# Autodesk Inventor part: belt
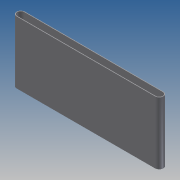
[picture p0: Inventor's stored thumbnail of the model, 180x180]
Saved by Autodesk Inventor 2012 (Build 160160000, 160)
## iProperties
Created: 2012-04
Part Number: belt
Material: Default
Document SubType Name: Modeling
Designer: win32
Mass: 4888.77 g
Surface Area: 19772.4 cm^2
Volume: 4888.77 cm^3
Density: 1 g/cm^3
Author: win32
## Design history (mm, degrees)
sketch "Sketch1"
  geometry: L1 (-244.095, 42.88)-(755.905, 42.88); L2 (755.905, 92.88)-(-244.095, 92.88); L3 (-244.095, 37.88)-(755.905, 37.88); L4 (755.905, 97.88)-(-244.095, 97.88); A1 r 25 centre (-244.095, 67.88) between (-244.095, 42.88) and (-244.095, 92.88) reference; A2 r 25 centre (755.905, 67.88) between (755.905, 42.88) and (755.905, 92.88) reference; A3 r 25 centre (755.905, 67.88) between (755.905, 42.88) and (755.905, 92.88); A4 r 25 centre (-244.095, 67.88) between (-244.095, 92.88) and (-244.095, 42.88); A5 r 30 centre (-244.095, 67.88) between (-244.095, 97.88) and (-244.095, 37.88); A6 r 30 centre (755.905, 67.88) between (755.905, 37.88) and (755.905, 97.88)
  constraints: 12 point on circle, 8 end point, 6 centre point, 5 tangent, 2 parallel, 1 coincident, 1 concentric, 1 vertical alignment, 4 other
  dimensions: "d0" = 5 distance between parallel lines of L1 L3
extrude "Extrusion1" new body sketch "Sketch1" stored distance "d1" = 450; taper "d2" = 0 deg
body "Solid1"
